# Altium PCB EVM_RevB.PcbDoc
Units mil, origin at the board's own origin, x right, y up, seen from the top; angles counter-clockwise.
Board outline 2000 x 3000 mil, 4 copper layers (Top Layer, Signal Layer 1, Signal Layer 2, Bottom Layer), stack 85.4 mil thick; 50 components, 21 nets, 126 pads, 89 vias.
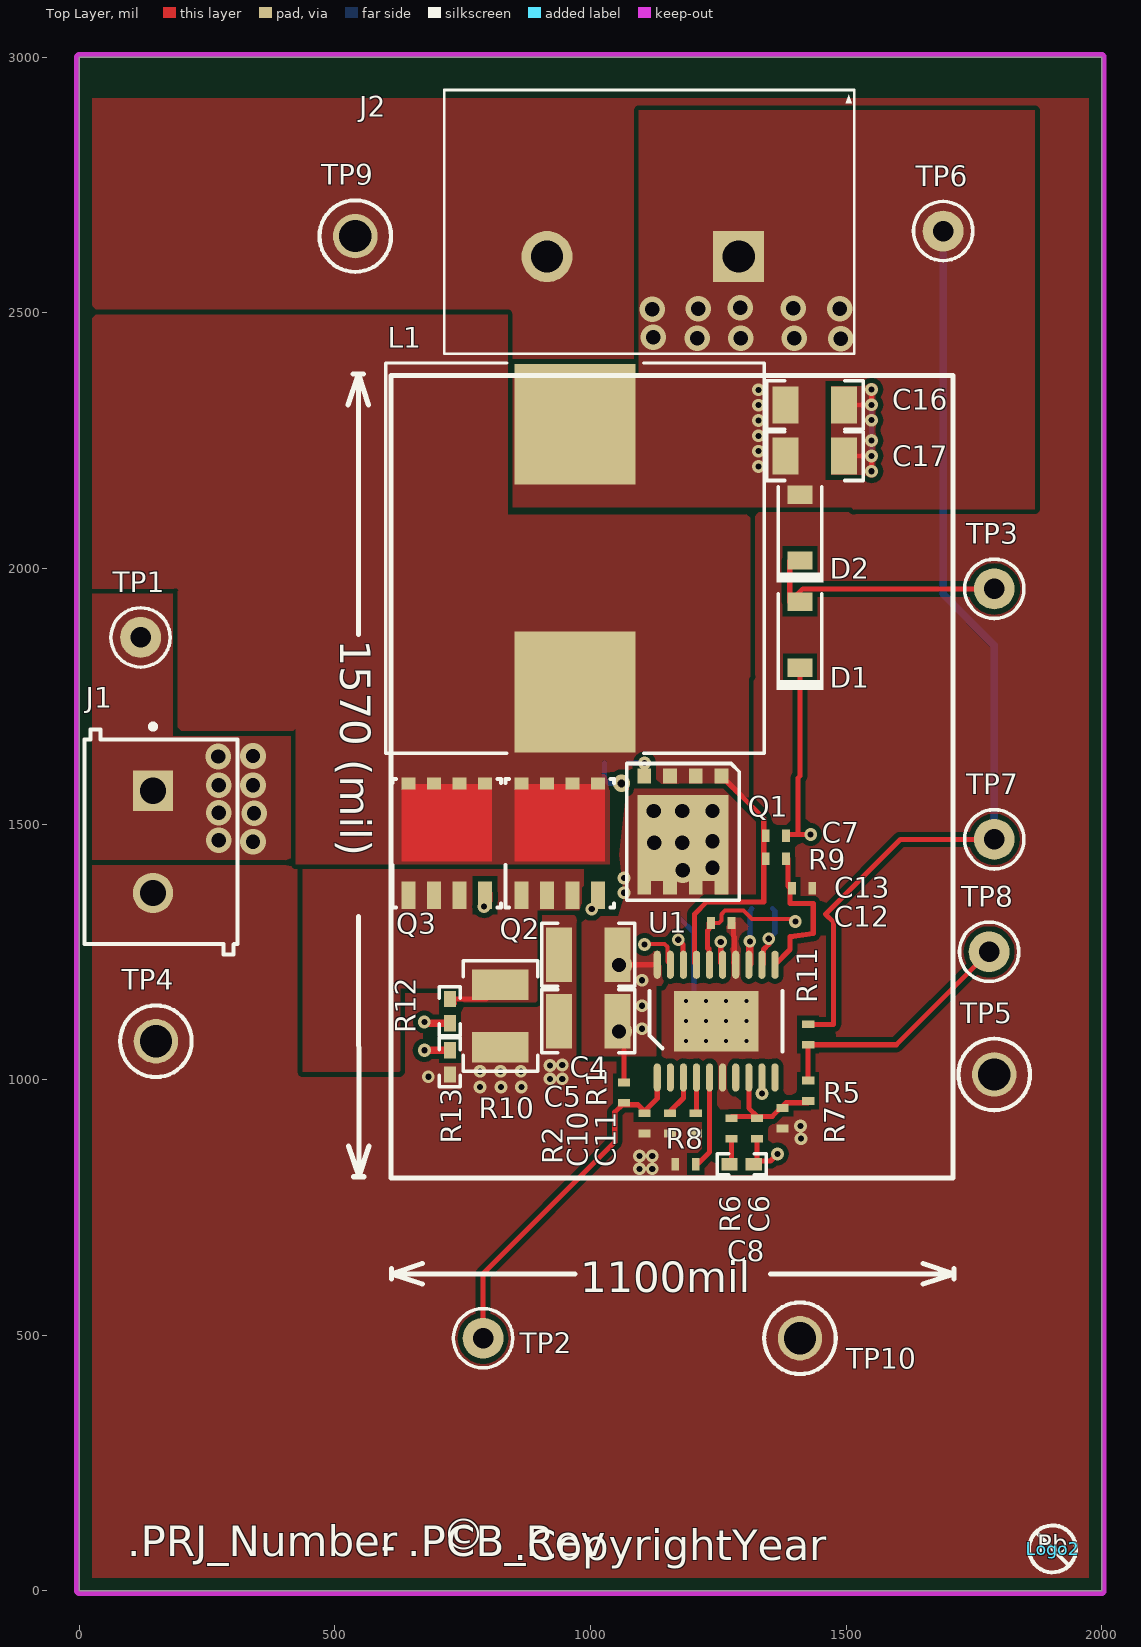
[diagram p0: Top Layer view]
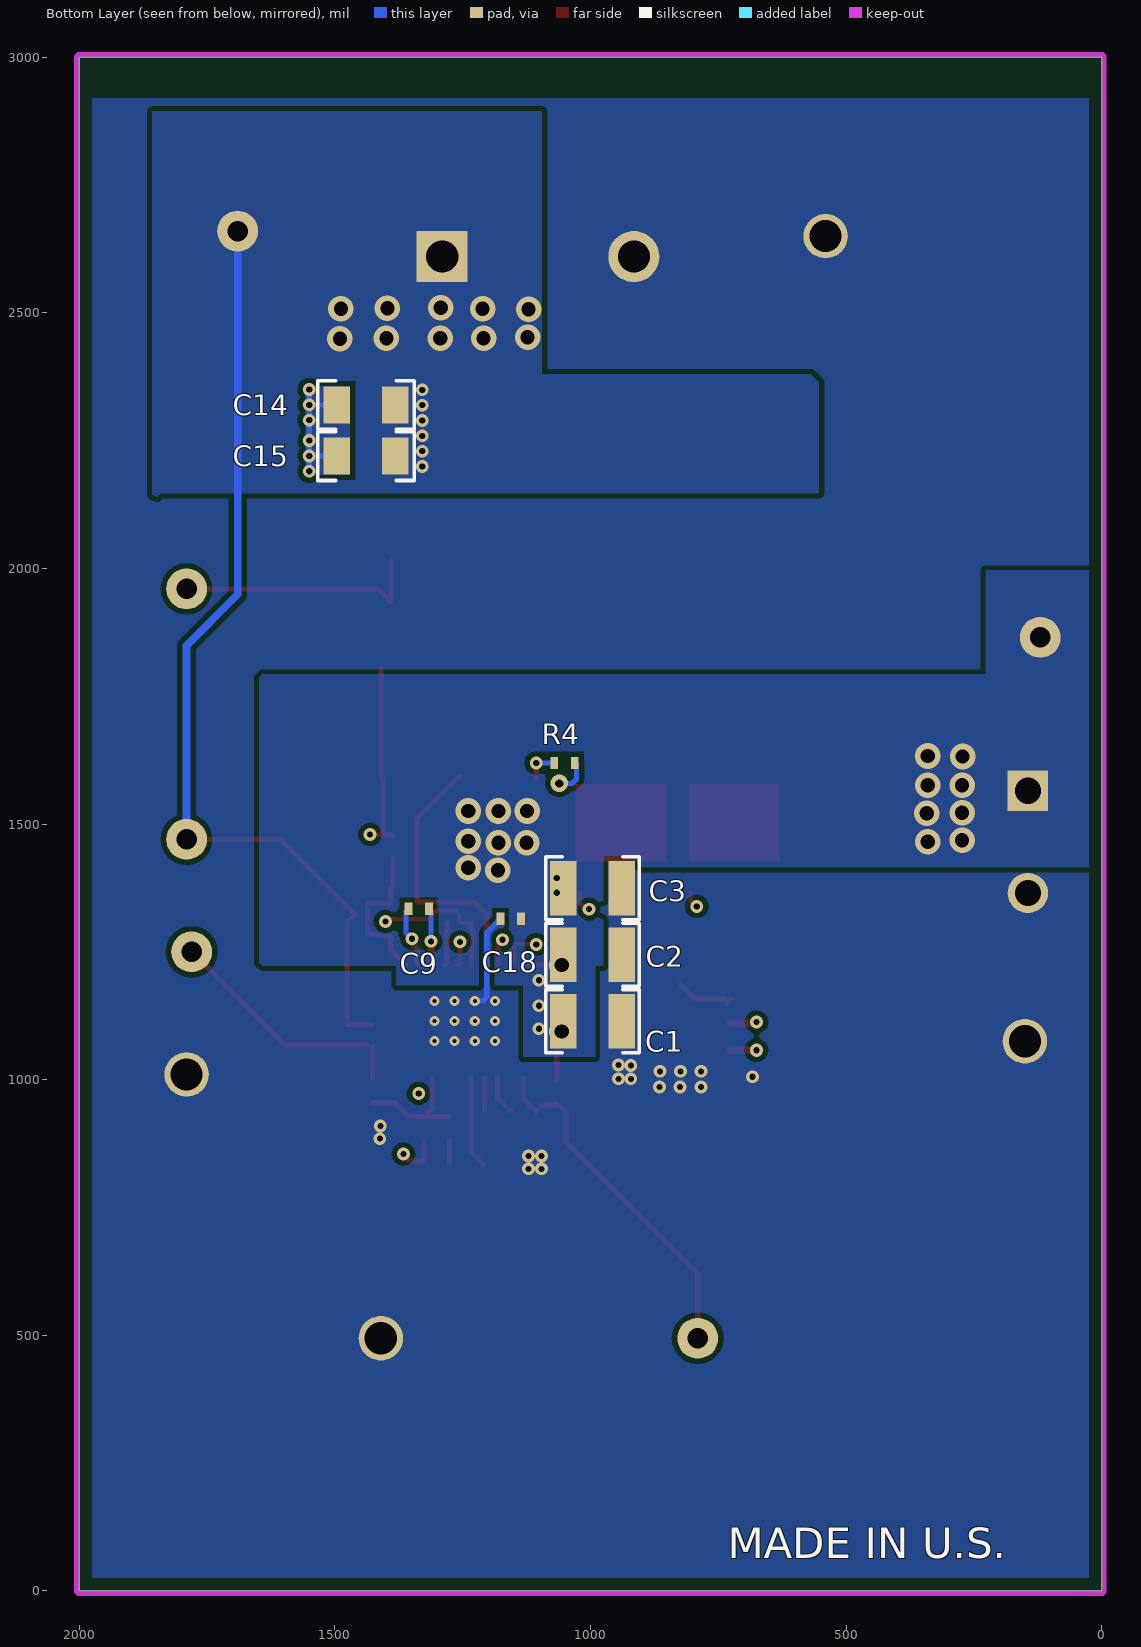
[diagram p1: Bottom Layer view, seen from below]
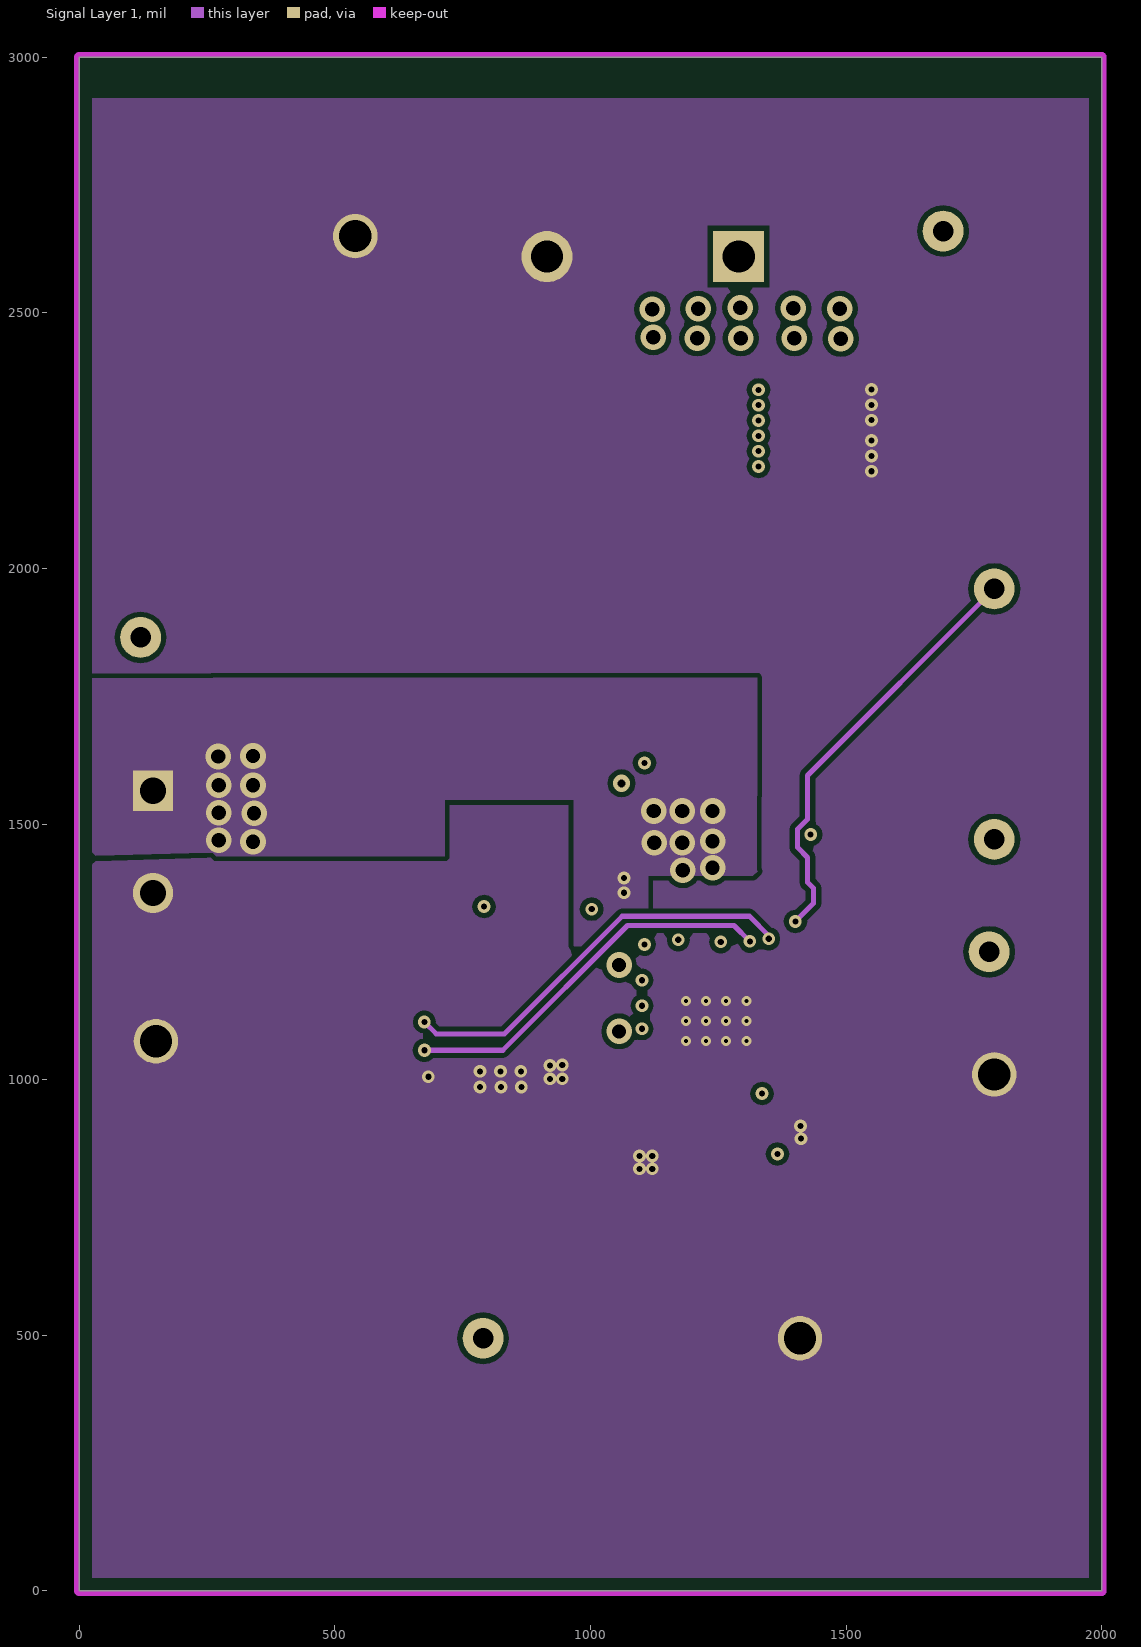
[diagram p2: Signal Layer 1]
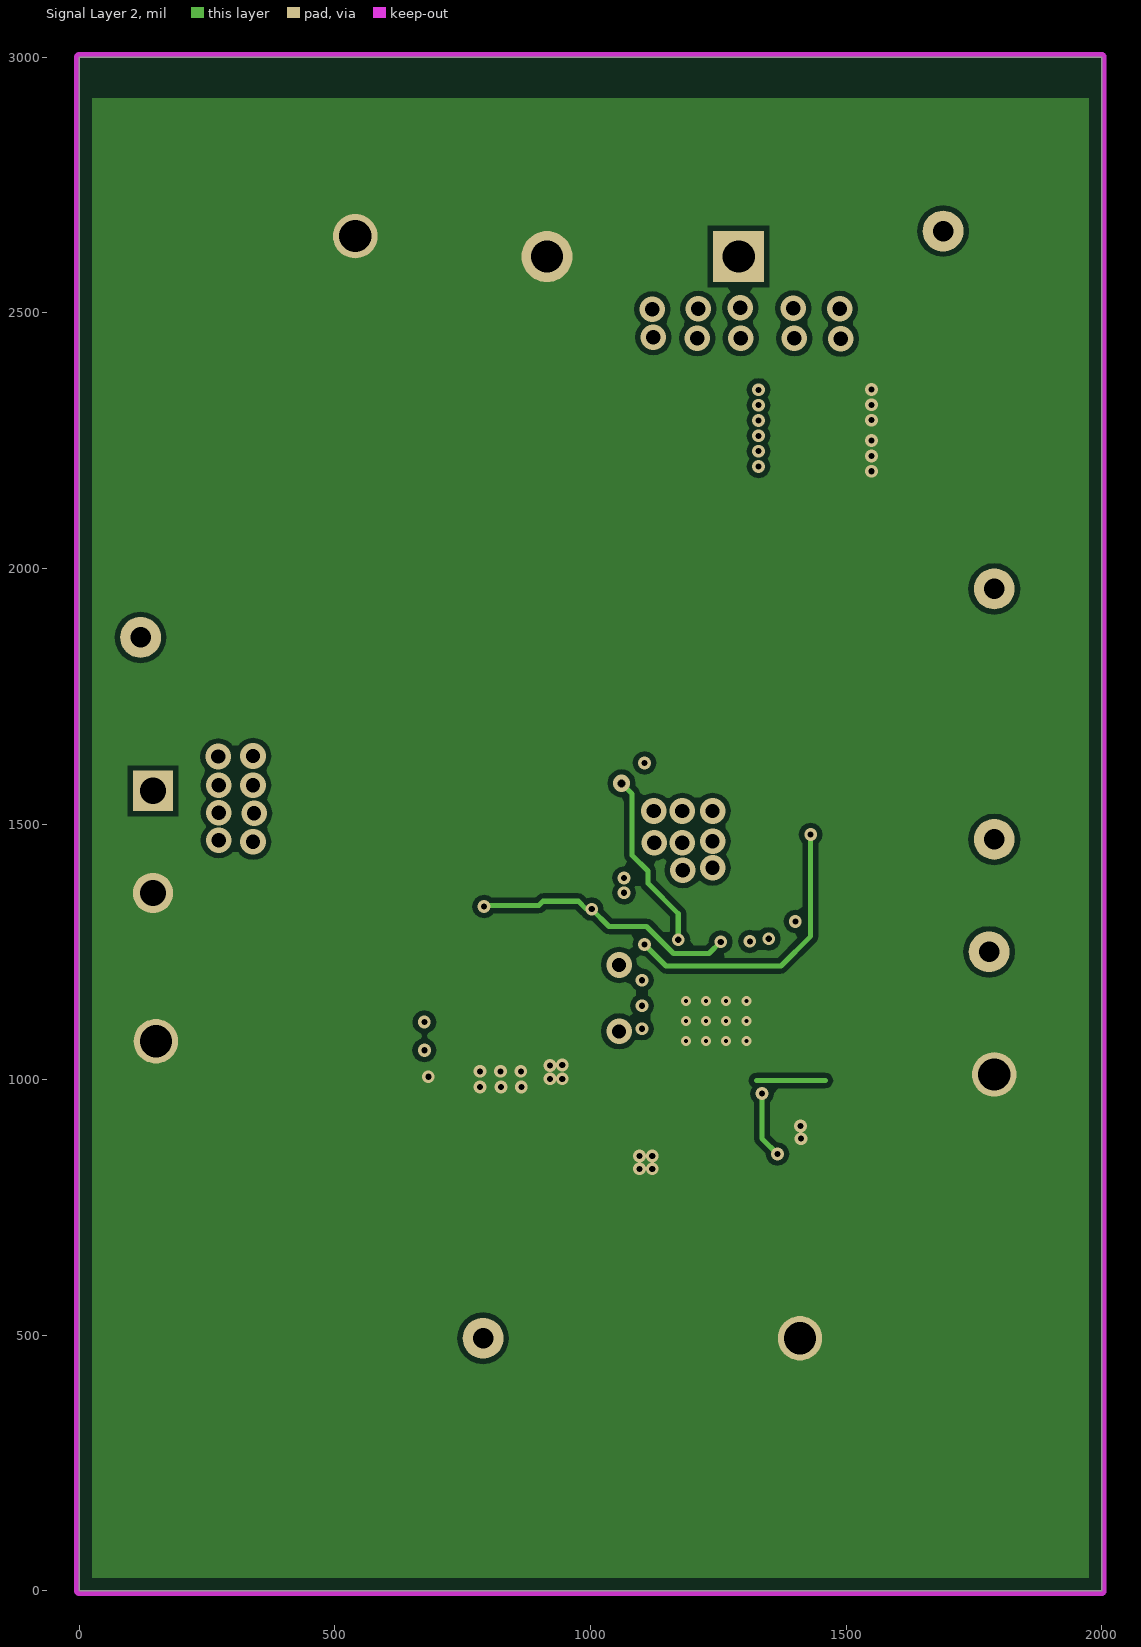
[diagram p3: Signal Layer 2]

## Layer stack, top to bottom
Top Solder: solder mask 0.4, Solder Resist, Dk 3.5
Top Layer: signal copper 2.8
Dielectric1: core 59.2, FR-4, Dk 4.8
Signal Layer 1: signal copper 2.8
Dielectric 3: prepreg 5, Dk 4.2
Signal Layer 2: signal copper 2.8
Dielectric 2: core 10, Dk 4.2
Bottom Layer: signal copper 2.8
Bottom Solder: solder mask 0.4, Solder Resist, Dk 3.5

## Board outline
0,0 2000,0 2000,3000 0,3000

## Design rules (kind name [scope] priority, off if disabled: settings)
AcuteAngle [All] p1: minimum=4.50000000000000E+0001 checktracksonly=FALSE
AssemblyTestPointUsage [All] p1: valid=2
Clearance Clearance_BoardEdge_MountingHoles [OnCopper and InComponentClass('Mounting Holes') vs IsKeepOut] p1: gap=40
Clearance Clearance_BoardEdge_Poly [OnCopper and InPoly vs IsKeepOut] p2: gap=25
Clearance Clearance_BoardEdge [OnCopper and Not InComponentClass('Logo') and not InComponentClass('FiducialMark') and not InRegion(1000,500,4000,800) and Not IsKeepout vs IsKeepOut] p3: gap=75
Clearance Clearance_Poly [InPolygon] p4: gap=10
Clearance [All] p5: gap=8
ComponentClearance ComponentClearance_ScrewToNut [(HasFootprint('NY PMS 440 0025 PH')) vs (HasFootprint('Keystone_1902C'))] p1: gap=5 collisioncheckmode=3 verticalgap=10 showdistances=FALSE
ComponentClearance ComponentClearance_MountingHoles [InComponentClass('Mounting Holes')] p2: gap=20 collisioncheckmode=3 verticalgap=100000 showdistances=FALSE
ComponentClearance ComponentClearance_SmallPassives [HasFootprint('0201*') or HasFootprint('0402*') or HasFootprint('0508') or HasFootprint('0603*') or HasFootprint('0612') or HasFootprint('0805*') or HasFootprint('0815*') or HasFootprint('0830*') or HasFootprint('1206*') or HasFootprint('1210*') or HasFootprint('1808*') or HasFootprint('1812*') or HasFootprint('1825*') or HasFootprint('2010*') or HasFootprint('2220*') or HasFootprint('2225*') or HasFootprint('2512*') or HasFootprint('2728*') or HasFootprint('3518*') vs HasFootprint('0201*') or HasFootprint('0402*') or HasFootprint('0508') or HasFootprint('0603*') or HasFootprint('0612') or HasFootprint('0805*') or HasFootprint('0815*') or HasFootprint('0830*') or HasFootprint('1206*') or HasFootprint('1210*') or HasFootprint('1808*') or HasFootprint('1812*') or HasFootprint('1825*') or HasFootprint('2010*') or HasFootprint('2220*') or HasFootprint('2225*') or HasFootprint('2512*') or HasFootprint('2728*') or HasFootprint('3518*')] p3: gap=10 collisioncheckmode=3 verticalgap=10 showdistances=FALSE
ComponentClearance ComponentClearance_THtoSMT [IsThruComponent vs IsSMTComponent] p4: gap=20 collisioncheckmode=3 verticalgap=100000 showdistances=FALSE
ComponentClearance ComponentClearance_THtoTH [IsThruComponent vs IsThruComponent] p5: gap=20 collisioncheckmode=3 verticalgap=100000 showdistances=FALSE
ComponentClearance [All] p6: gap=20 collisioncheckmode=3 verticalgap=10 showdistances=FALSE
DiffPairsRouting [All] p1: maxlimit=100 minlimit=10 mostfreqgap=10 toplayer_minwidth=15 toplayer_maxwidth=15 toplayer_prefwidth=15 midlayer1_minwidth=15 midlayer1_maxwidth=15 midlayer1_prefwidth=15 midlayer2_minwidth=15 midlayer2_maxwidth=15 midlayer2_prefwidth=15 bottomlayer_minwidth=15 bottomlayer_maxwidth=15 bottomlayer_prefwidth=15 maxuncoupledlength=1000
FabricationTestPointUsage TestPointUsage [All] p1: valid=2 allowmultiple=FALSE
FabricationTestpoint Testpoint [All] p1: side=3 testpointundercomponent=TRUE minsize=40 maxsize=100 preferedsize=60 minholesize=0 maxholesize=40 preferedholesize=32 testpointgrid=1 allowsidetop=TRUE allowsidebottom=TRUE usegrid=TRUE gridtolerance=0.01
FanoutControl Fanout_LCC [IsLCC] p1: bgadir=Out bgaviamode=Centered fanoutstyle=Auto fanoutdirection=Alternating viagrid=1 // Fanout_LCC (Default Rule)
FanoutControl Fanout_BGA [IsBGA] p2: bgadir=Out bgaviamode=Centered fanoutstyle=Auto fanoutdirection=Alternating viagrid=1 // Fanout_BGA (Default Rule)
FanoutControl Fanout_Default [All] p4: bgadir=Out bgaviamode=Centered fanoutstyle=Auto fanoutdirection=Alternating viagrid=1 // Fanout_Default (Default Rule)
FanoutControl Fanout_Small [(CompPinCount < 5)] p5: bgadir=Out bgaviamode=Centered fanoutstyle=Auto fanoutdirection=OutThenIn viagrid=1 // Fanout_Small (Default Rule)
HoleSize [All] p1: absolutevalues=TRUE maxlimit=251 minlimit=7 maxpercent=80.000 minpercent=20.000
MinimumAnnularRing [All] p1: minimumring=5
MinimumSolderMaskSliver MinimumSolderMaskSliver_Logo [InComponentClass('Logo') vs InComponentClass('Logo')] p1: minsoldermaskwidth=0
MinimumSolderMaskSliver SilkscreenOverComponentPads [All] p2: minsoldermaskwidth=0
MinimumSolderMaskSliver [All] p3: minsoldermaskwidth=0
PlaneConnect [All] p1: planeconnectstyle=Direct reliefexpansion=10 reliefentries=4 reliefconductorwidth=10 reliefairgap=10
PolygonConnect [All] p1: connectstyle=Direct reliefconductorwidth=10 reliefentries=4 polygonreliefangle="90 Angle" airgapwidth=10
RoutingVias [All] p1: holewidth=16 width=34 viastyle="Through Hole" minholewidth=7 minwidth=19 maxholewidth=40 maxwidth=65
SMDToCorner [All] p1: distance=0
SilkToSilkClearance [All] p1: silktosilkclearance=0
SilkToSolderMaskClearance [IsPad] p1: minsilkscreentomaskgap=0 clearancetoexposedcopper=TRUE
SolderMaskExpansion [All] p1: expansion=3
UnpouredPolygon [All] p1: allowunpoured=FALSE
Width [All] p1: maxlimit=100 minlimit=6 preferedwidth=10 checkconnectedcopper=TRUE
15 further rules are at their usual default settings.

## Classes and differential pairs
component class EVM_Hardware: Logo2
differential pair CS: +CS_P -CS_N

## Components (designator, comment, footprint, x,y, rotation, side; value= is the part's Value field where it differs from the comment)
C1 "GRM32ER71H106KA12L" 1210 995.91,1114.45 r180 bottom
C2 "GRM32ER71H106KA12L" 1210 995.91,1244.45 r180 bottom
C3 "GRM32ER71H106KA12L" 1210 995.91,1374.45 r180 bottom
C4 "GRM32ER71H106KA12L" 1210 995.91,1244.45 r180 top
C5 "GRM32ER71H106KA12L" 1210 995.91,1114.45 r180 top
C6 "CC0402JRNPO9BN101" 0402S 1325.91,904.45 r90 top
C7 "C1005X7R1H104K050BB" 0402S 1362.75,1476.93 r0 top
C8 "GRM155R61C103KA01D" 0402 1295.91,834.45 r180 top
C9 "GRM155R72A102KA01D" 0402S 1335.91,1334.45 r180 bottom
C10 "GRM155C80G474KE01D" 0402S 1155.91,914.45 r270 top
C11 "C1005X5R1C105K050BC" 0402S 1205.91,914.45 r270 top
C12 "GRM155R61E475ME15" 0402S 1255.91,1306.45 r180 top
C13 "GRM155R72A102KA01D" 0402S 1414.25,1374.45 r0 top
C14 "C3216X5R1E476M160AC" 1206 1439,2319.69 r0 bottom
C15 "C3216X5R1E476M160AC" 1206 1439,2219.69 r0 bottom
C16 "C3216X5R1E476M160AC" 1206 1439,2319.69 r0 top
C17 "C3216X5R1E476M160AC" 1206 1439,2219.69 r0 top
C18 "C1005X7R1H104K050BB" 0402S 1155.91,1314.45 r0 bottom
D1 "1N5819HW-7-F" SOD-123 1410,1870 r90 top
D2 "1N5819HW-7-F" SOD-123 1410,2080 r90 top
J1 "OSTTC022162" On-Shore_OSTTC022162 160,1465 r270 top
J2 "OSTT7022150" TERM_BLK_OSTT7022150 1290,2610 r180 top
L1 "74435571100" WE-HCB_1890 970,2020 r90 top
Logo2 "Pb-Free Symbol" Pb-Free_Overlay_Small 1904,82 r0 top
Q1 "CSD18563Q5A" TRANS_NexFET_Q5A 1180.91,1484.45 r270 top
Q2 "CSD18532Q5B" TRANS_NexFET_Q5B 940,1470 r90 top
Q3 "CSD18532Q5B" TRANS_NexFET_Q5B 719,1470 r90 top
R1 "CRCW0402100KFKED" 0402S 1065.91,974.45 r90 top
R2 "CRCW04029K76FKED" 0402S 1105.91,914.45 r270 top
R4 "CRCW04020000Z0ED" 0402S 1050.91,1619.45 r0 bottom
R5 "CRCW040210K5FKED" 0402S 1425.91,978.25 r270 top
R6 "CRCW04023K48FKED" 0402S 1275.91,904.45 r270 top
R7 "CRCW0402750RFKED" 0402S 1375.91,924.45 r90 top
R8 "CRCW040224K9FKED" 0402S 1185.91,834.45 r0 top
R9 "CRCW0402133KFKED" 0402S 1362.75,1431.93 r180 top
R10 "PMR25HZPFU5L00" 1210M 823.91,1124.45 r90 top
R11 "CRCW040249R9FKED" 0402S 1425.91,1088.25 r90 top
R12 "CRCW0402100RFKED" 0402 725.09,1133.83 r90 top
R13 "CRCW0402100RFKED" 0402 725.09,1033.83 r270 top
TP1 "5000" Keystone5000 120,1865 r180 top
TP2 "5000" Keystone5000 790,494 r0 top
TP3 "5000" Keystone5000 1790,1960 r0 top
TP4 "5011" Keystone5011 150,1075 r180 top
TP5 "5011" Keystone5011 1790,1010 r0 top
TP6 "5000" Keystone5000 1690,2660 r180 top
TP7 "5000" Keystone5000 1790,1470 r0 top
TP8 "5000" Keystone5000 1780,1250 r0 top
TP9 "5011" Keystone5011 540,2650 r180 top
TP10 "5011" Keystone5011 1410,494 r0 top
U1 "LM5117QPMH/NOPB" PWP0020A_L 1245.91,1114.45 r90 top

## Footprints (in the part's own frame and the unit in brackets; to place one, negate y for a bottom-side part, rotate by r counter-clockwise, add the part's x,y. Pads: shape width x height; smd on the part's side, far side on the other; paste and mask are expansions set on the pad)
0402 [mm] "0402 from SM-752 data"
  rect 0.8x0.6 smd: 1(-0.6,0) 2(0.6,0)
  silkscreen extent -1.22,-0.52 1.22,0.52, body extent -0.55,-0.3 0.55,0.3, height 0.6
0402S [mil] "Based on C0402S footprint from PADS legacy"
  rect 15x24 smd: 1(-20,0) 2(20,0)
  body extent -22,-12 22,12, height 24
1206 [mm] "1206 from SM-752 data"
  rect 1.3x1.85 smd: 1(-1.45,0) 2(1.45,0)
  silkscreen extent -2.4,-1.21 2.4,1.21, body extent -1.7,-0.9 1.7,0.9, height 1.35
1210 [mm] "1210 from SM-752 data"
  rect 1.3x2.7 smd: 1(-1.45,0) 2(1.45,0)
  silkscreen extent -2.32,-1.57 2.32,1.57, body extent -1.7,-1.35 1.7,1.35, height 1.35
1210M [mm] "1210 from SM-752 data"
  rect 1.5x2.8 smd: 1(-1.55,0) 2(1.55,0)
  silkscreen extent -2.75,-1.85 2.75,1.85, body extent -1.7,-1.35 1.7,1.35, height 1.35
Keystone5000 [mil] "For Keystone 500x miniature loop terminals"
  round 80 hole 40: 1(0,0)
  silkscreen extent -58,-58 58,58, body extent -49,-49 49,49, height 182
Keystone5011 [mil] "Keystone Multipurpose loops"
  round 87 hole 63: 1(0,0)
  silkscreen extent -70,-70 70,70, body extent -63,-63 63,62, height 319
On-Shore_OSTTC022162 [mm] "THD, 2-Leads, Body 10.16x7.6mm, Pitch 5.08mm"
  rect 2x2 hole 1.3: 1(-2.54,-0.4)
  round 2 hole 1.3: 2(2.54,-0.4)
  silkscreen extent -5.85,-3.8 5.6,3.8, body extent -5.58,-3.8 5.6,3.8, height 10.31
Pb-Free_Overlay_Small [mil]
  silkscreen extent -46,-46 46,46
PWP0020A_L [mm] "TSOP, 20-Leads, Body 6.5x4.4mm, Pitch 0.65mm, Exposed Pad, IPC High Density"
  oval 1.4x0.35 smd: 1(-2.8,2.925) 2(-2.8,2.275) 3(-2.8,1.625) 4(-2.8,0.975) 5(-2.8,0.325) 6(-2.8,-0.325) 7(-2.8,-0.975) 8(-2.8,-1.625) 9(-2.8,-2.275) 10(-2.8,-2.925) 11(2.8,-2.925) 12(2.8,-2.275) 13(2.8,-1.625) 14(2.8,-0.975) 15(2.8,-0.325) 16(2.8,0.325) 17(2.8,0.975) 18(2.8,1.625) 19(2.8,2.275) 20(2.8,2.925)
  rect 3x4.2 smd: 21(0,0)
  silkscreen extent -1.5,-3.3 1.5,3.3, body extent -3.21,-3.25 3.21,3.25, height 0.98
SOD-123 [mm] "On Semi recommended land pattern"
  rect 0.915x1.22 smd: 1(-1.637,0) 2(1.637,0)
  silkscreen extent -2.74,-1.17 2.03,1.17, body extent -1.93,-0.9 1.93,0.9, height 1.35
TERM_BLK_OSTT7022150 [mm]
  rect 2.54x2.54 hole 1.6: 1(0,0)
  round 2.54 hole 1.6: 2(9.525,0)
  silkscreen extent -5.74,-8.28 14.63,4.83, body extent -5.3,-8 14.33,4.5, height 21.6
TRANS_NexFET_Q5A [mm] "TI recommended land pattern (nominal) M0139-01"
  rect 0.75x0.675 smd paste-0.1 mask+0.051: 1(-2.776,1.917) 2(-2.776,0.639) 3(-2.776,-0.639) 4(-2.776,-1.917)
  rect 0.655x0.675 smd paste-0.1 mask+0.051: 5(2.776,-1.917) 6(2.776,-0.639) 7(2.776,0.639) 8(2.776,1.917)
  rect 4.295x4.51 smd paste-2.2 mask+0.051: 9(0.301,0)
  silkscreen extent -3.4,-2.8 3.4,2.8, body extent -3.05,-2.5 3.05,2.5, height 1.11
TRANS_NexFET_Q5B [mm] "TI recommended land pattern (nominal) November 2012"
  rect 1.372x0.71 smd paste-0.4: 1(-2.776,1.905) 2(-2.776,0.635) 3(-2.776,-0.635) 4(-2.776,-1.905)
  rect 0.59x0.71 smd paste-0.3: 5(2.776,-1.905) 6(2.776,-0.635) 7(2.776,0.635) 8(2.776,1.905)
  Top Layer region: -1.106,-2.26 2.744,-2.26 2.744,2.26 -1.106,2.26
  silkscreen extent -3.38,-2.7 3,2.7, body extent -3.23,-2.55 2.87,2.55, height 1.06
WE-HCB_1890 [mm] "WURTH ELEKTRONIK"
  rect 6x6 smd: 1(-6.65,0) 2(6.65,0)
  silkscreen extent -9.7,-9.4 9.7,9.4, body extent -9.65,-9.35 9.65,9.35, height 9.2

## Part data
C1 C2 C3 C4 C5: "CAP, CERM, 10 µF, 50 V, +/- 10%, X7R, 1210"
C6: "CAP, CERM, 100 pF, 50 V, +/- 5%, C0G/NP0, 0402"
C7 C18: "CAP, CERM, 0.1 µF, 50 V, +/- 10%, X7R, 0402"
C8: "CAP, CERM, 0.01 µF, 16 V, +/- 10%, X5R, 0402"
C9 C13: "CAP, CERM, 1000 pF, 100 V, +/- 10%, X7R, 0402"
C10: "CAP, CERM, 0.47 µF, 4 V, +/- 10%, X6S, 0402"
C11: "CAP, CERM, 1 µF, 16 V, +/- 10%, X5R, 0402"
C12: "CAP, CERM, 4.7 µF, 25 V, +/- 20%, X5R, 0402"
C14 C15 C16 C17: "CAP, CERM, 47 µF, 25 V, +/- 20%, X5R, 1206"
D1 D2: "Diode, Schottky, 40 V, 1 A, SOD-123"
J1: "Terminal Block, 2-pole, 200mil, TH"
J2: "Terminal Block, 30A, 9.52mm (.375) Pitch, 2-Pos, TH"
L1: "Inductor, Shielded Drum Core, Ferrite, 10 µH, 16.5 A, 0.0069 ohm, SMD"
Logo2: library part Pb-Free
Q1: "MOSFET, N-CH, 60 V, 15 A, SON 5x6mm"
Q2 Q3: "MOSFET, N-CH, 60 V, 172 A, SON 5x6mm"
R1: "RES, 100 k, 1%, 0.063 W, 0402"
R2: "RES, 9.76 k, 1%, 0.063 W, 0402"
R4: "RES, 0, 5%, 0.063 W, 0402"
R5: "RES, 10.5 k, 1%, 0.063 W, 0402"
R6: "RES, 3.48 k, 1%, 0.063 W, 0402"
R7: "RES, 750, 1%, 0.063 W, 0402"
R8: "RES, 24.9 k, 1%, 0.063 W, 0402"
R9: "RES, 133 k, 1%, 0.063 W, 0402"
R10: "RES, 0.005, 1%, 1 W, 1210"
R11: "RES, 49.9, 1%, 0.063 W, 0402"
R12 R13: "RES, 100, 1%, 0.063 W, 0402"
TP1 TP2 TP3 TP6 TP7 TP8: "Test Point, Miniature, Red, TH"
TP4 TP5 TP9 TP10: "Test Point, Multipurpose, Black, TH"
U1: "Wide Input Range Synchronous Buck Controller with Analog Current Monitor, PWP0020A"

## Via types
v1: diameter 25, hole 12, Top Layer to Bottom Layer, 47 vias
v2: diameter 50, hole 28, Top Layer to Bottom Layer, 28 vias
v3: diameter 19.68, hole 7.87, Top Layer to Bottom Layer, 12 vias
v4: diameter 34, hole 16, Top Layer to Bottom Layer, 1 vias
v5: diameter 26, hole 12, Top Layer to Bottom Layer, 1 vias

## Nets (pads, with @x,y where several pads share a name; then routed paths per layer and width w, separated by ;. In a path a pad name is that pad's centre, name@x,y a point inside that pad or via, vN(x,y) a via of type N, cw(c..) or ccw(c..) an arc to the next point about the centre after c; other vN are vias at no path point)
12VOUT: C14.1 C15.1 C16.1 C17.1 D2.2 J2.1 L1.2 R11.2 TP6.1 TP7.1 | length 1850.4
  Top Layer w10: R11.2@1429.71,1108.07 1475.91,1108.07 1475.91,1307.71 1460,1323.62 1606.38,1470 TP7.1
  Bottom Layer w15: 1690,2620 1690,1949.25 1790,1849.25 TP7.1
  other v1: 1329,2199.37 1329,2229.37 1329,2259.37 1329,2289.37 1329,2319.37 1329,2349.37
  other v2: 1490,2449 1209,2450 1294,2450 1399,2450 1123,2452 1121,2507 1211,2508 1488,2508 1397,2509 1293,2510
CS_N: C9.2 R13.1 U1.13 | length 909.8
  Top Layer w15: v5(675.27,1057.46) R13.1 ; U1.13@1311.91,1226.71 v1(1311.91,1270.45)
  Signal Layer 1 w10: v5(675.27,1057.46) 828.6,1057.46 1072.59,1301.45 1280.91,1301.45 v1(1311.91,1270.45)
  Bottom Layer w10: v1(1311.91,1270.45) 1311.91,1330.45 C9.2
CS_P: C9.1 R12.1 U1.12 | length 956.2
  Top Layer w10: U1.12@1338.8,1226.58 1338.8,1254.57 v1@1348.91,1264.68
  Top Layer w15: v1@677.52,1110.21 R12.1
  Signal Layer 1 w10: v1(675.09,1112.63) 698.28,1089.45 832.12,1089.45 1062.12,1319.45 1311.07,1319.45 1348.91,1281.6 v1(1348.91,1275.45)
  Bottom Layer w10: v1(1348.91,1275.45) 1360.59,1287.13 1360.59,1329.76 C9.1
GND: C1.2 C2.2 C3.2 C4.2 C5.2 C10.2 C11.2 C12.1 C13.2 C14.2 C15.2 C16.2 C17.2 C18.2 J1.2 J2.2 R2.2 R7.1 R8.1 R10.1 R13.2 TP4.1 TP5.1 TP9.1 TP10.1 U1.6 U1.14 U1.21 | length 710.8
  Top Layer w10: C12.1@1279.53,1306.45 1280.03,1305.94 1280.03,1280.21 1281.28,1278.96 1281.28,1228.94 1280.03,1228.94 U1.14 ; C17.2 v1@1549.69,2219.69 ; C16.2 v1@1549.69,2319.69 ; v1(1550,2190) v1(1550,2220) ; v1(1550,2320) v1(1550,2350)
  Bottom Layer w10: C18.2 1202.7,1287.66 1202.7,1161.24 1210.12,1153.82 v3(1226.22,1153.82) ; C15.2 v1@1549.69,2219.69 ; C14.2 v1@1549.69,2319.69 ; v1(1550,2190) v1(1550,2220) v1(1550,2250) v1(1550,2290) v1(1550,2320) v1(1550,2350)
  other v1: 1095.91,825.45 1120.91,825.45 1095.91,850.45 1120.91,850.45 1411.91,884.45 1410.91,909.45 783.91,985.45 824.91,985.45 864.91,985.45 920.91,1001.45 944.91,1001.45 682.91,1005.45 783.91,1016.18 823.91,1016.18 863.91,1016.18 920.91,1027.45 944.91,1028.45
  other v3: 1186.85,1075.08 1226.22,1075.08 1265.59,1075.08 1304.96,1075.08 1186.85,1114.45 1226.22,1114.45 1265.59,1114.45 1304.96,1114.45 1186.85,1153.82 1265.59,1153.82 1304.96,1153.82
NetC6_1: C6.1 C8.1 U1.9 | length 216.3
  Top Layer w10: C6.1@1325.91,880.83 1325.91,840.83 1352.29,840.83 v1(1365.91,854.45)
  Signal Layer 2 w10: v1(1335.91,972.72) 1335.91,884.45 v1(1365.91,854.45)
NetC6_2: C6.2 R5.2 R6.1 R7.2 U1.8 | length 243.8
  Top Layer w10: R6.1@1275.91,928.07 C6.2@1325.91,928.07 ; U1.8 1309.88,944.09 C6.2@1325.91,928.07 ; R5.2@1425.91,954.62 1382.46,954.62 1375.91,948.07 1355.91,928.07 C6.2@1325.91,928.07
NetC7_1: C7.1 L1.1 Q1.1 Q1.2 Q1.3 Q2.5 Q2.6 Q2.7 Q2.8 Q3.5 Q3.6 Q3.7 Q3.8 R9.2 U1.17 | length 526.3
  Top Layer w10: U1.17 1203.66,1228.54 1203.66,1323.59 1227.74,1347.67 1339.13,1347.67 1339.13,1431.93 1339.13,1511.02 Q1.1
NetC7_2: C7.2 D1.1 U1.19 | length 1016.7
  Top Layer w8: v1@1106.58,1265.12 1145.24,1265.12 1150.53,1259.82 1150.53,1230.49 U1.19
  Top Layer w10: C7.2@1386.38,1476.93 1388.89,1479.45 1405.91,1479.45 ; 1405.91,1589.98 1405.91,1479.45 ; 1410,1594.07 D1.1 ; v1(1430.91,1479.45) 1405.91,1479.45
  Signal Layer 2 w10: v1(1105.91,1264.45) 1147.98,1222.37 1372.69,1222.37 1430.91,1280.59 v1(1430.91,1479.45)
NetC8_2: C8.2 R6.2 | length 42.8
  Top Layer w10: C8.2@1275.91,838.07 R6.2@1275.91,880.83
NetC10_1: C10.1 U1.3 | length 76.9
  Top Layer w10: C10.1@1155.91,938.07 1181.93,964.09 U1.3
NetC11_1: C11.1 U1.4 | length 64.5
  Top Layer w10: C11.1@1207.52,939.68 U1.4
NetC13_1: C13.1 R9.1 U1.11 | length 306
  Top Layer w10: U1.11 1390.63,1254.25 1390.63,1279.45 1435.86,1285.54 1435.86,1344.4 1390.63,1344.4 1390.63,1374.45 1386.38,1378.7 R9.1@1386.38,1431.93
NetQ1_4: Q1.4 R4.2 | length 62.6
  Top Layer w10: Q1.4@1105.91,1588.26 v1(1105.91,1619.45)
  Bottom Layer w10: R4.2@1074.53,1619.45 v1(1105.91,1619.45)
NetQ2_1: Q2.1 Q2.2 Q2.3 Q3.1 Q3.2 Q3.3 R10.2 R12.2 | length 111.1
  Top Layer w10: R12.2 R12.2@733.89,1148.66 ; 736.9,1157.46 795.89,1157.46 R10.2
NetQ2_4: Q2.4 Q3.4 U1.15 | length 635
  Top Layer w10: v1(791.91,1338.45) 803.4,1349.94 Q3.4@803.4,1365.14 ; v1(1002.53,1333.37) 1007.96,1333.37 1021.4,1346.81 Q2.4@1021.4,1365.14 ; v1(1254.91,1269.45) 1254.91,1228.48 U1.15
  Signal Layer 2 w10: v1@795.91,1340.45 898.85,1340.45 907.35,1348.95 976.47,1348.95 992.04,1333.37 v1(1002.53,1333.37) 1036.46,1299.45 1109.85,1299.45 1162.79,1246.51 1231.97,1246.51 v1(1254.91,1269.45)
NetR1_1: R1.1 R2.1 TP2.1 U1.1 | length 685.7
  Top Layer w10: TP2.1 790,620 1047.56,878 1047.56,936.1 R1.1@1058.41,946.95 ; R1.1@1065.91,950.83 1093.15,950.83 1105.91,938.07 1130.75,962.91 U1.1
NetR4_1: R4.1 U1.18 | length 499.8
  Top Layer w10: v4(1060.91,1579.45) v4@1070.87,1569.49 ; v1@1175.91,1269.45 1180.91,1264.45 1180.91,1225.71 U1.18
  Signal Layer 2 w10: v4@1060.91,1567.26 v4(1060.91,1579.45) 1081.41,1558.95 1081.41,1460.05 1081.45,1460.01 1081.45,1438.81 1112.42,1407.83 1112.42,1383.96 1171.91,1324.47 v1(1171.91,1273.45)
  Bottom Layer w10: R4.1@1027.29,1619.45 1027.29,1588.03 1035.87,1579.45 v4(1060.91,1579.45) ; v1(1171.91,1273.45) v1@1175.91,1269.45
NetR5_1: R5.1 R11.1 TP8.1 | length 480.1
  Top Layer w10: R5.1@1425.91,1001.87 R11.1@1425.91,1064.63 ; 1437.91,1068.25 1598.25,1068.25 TP8.1
NetR8_2: R8.2 U1.5 | length 179.5
  Top Layer w10: R8.2@1209.53,834.45 1233.11,858.03 U1.5
VCC: C12.2 D1.2 D2.1 TP3.1 U1.16 | length 1602.4
  Top Layer w8: C12.2@1232.29,1306.45 C12.2 1251.91,1306.45 1256.41,1310.95 1256.41,1323.42 1263.44,1330.45 1299.88,1330.45 1315.88,1314.45 v1@1395.89,1314.45
  Top Layer w10: C12.2@1232.29,1306.45 1232.29,1294.45 1229.41,1291.57 1229.41,1256.31 1229.53,1256.19 1232.29,1256.19 1232.29,1225.51 U1.16 ; D2.1@1390,2015.53 1390,1934.47 1415.53,1960 TP3.1
  Signal Layer 1 w10: v1(1400.91,1309.45) 1436.12,1344.66 1436.12,1374.66 1424.68,1386.1 1424.68,1434.67 1405.41,1453.95 1405.41,1490.01 1424.68,1509.28 1424.68,1594.68 TP3.1
VIN: C1.1 C2.1 C3.1 C4.1 C5.1 C18.1 J1.1 Q1.5 Q1.6 Q1.7 Q1.8 Q1.9 R1.2 TP1.1 U1.20 | length 186.2
  Top Layer w10: C4.1 1072.76,1224.68 U1.20 ; v2(1056.03,1094.22) 1065.91,1084.34 R1.2@1065.91,998.07
  other v1: 1100.91,1099.45 1100.91,1144.45 1100.91,1194.45 1065.91,1365.45 1065.91,1394.45
  other v2: 1056.03,1224.22 1180.91,1409.45 1238.91,1414.45 1124.91,1463.45 1179.91,1463.45 340,1465 1238.91,1466.45 273,1468 342,1521 273,1522 1123.91,1525.45 1179.91,1525.45 1238.91,1525.45 273,1576 340,1576 272,1632 340,1633
pads on no net: U1.2 U1.7 U1.10
copper on no net: | length 104184.8
  Signal Layer 2 w10: 1325.35,998.22 1459.42,998.22
  Bottom Layer w1: 13159.2,6090.32 13258.89,6190 13378.89,6310 13498.89,6430 13618.89,6550 13738.89,6670 13858.89,6790 13978.89,6910 14098.89,7030 14218.89,7150 14278.89,7210 ; 13159.2,6150.32 13198.89,6190 13318.89,6310 13438.89,6430 13558.89,6550 13678.89,6670 13798.89,6790 13918.89,6910 14038.89,7030 14158.89,7150 14278.89,7270 ; 13159.2,6210.32 13258.89,6310 13378.89,6430 13498.89,6550 13618.89,6670 13738.89,6790 13858.89,6910 13978.89,7030 14098.89,7150 14218.89,7270 14278.89,7330 ; 13159.2,6270.32 13198.89,6310 13318.89,6430 13438.89,6550 13558.89,6670 13678.89,6790 13798.89,6910 13918.89,7030 14038.89,7150 14158.89,7270 14278.89,7390 ; 13159.2,6330.32 13258.89,6430 13378.89,6550 13498.89,6670 13618.89,6790 13738.89,6910 13858.89,7030 13978.89,7150 14098.89,7270 14218.89,7390 ; 13159.2,6390.32 13198.89,6430 13318.89,6550 13438.89,6670 13558.89,6790 13678.89,6910 13798.89,7030 13918.89,7150 14038.89,7270 14158.89,7390 ; 13159.2,6450.32 13258.89,6550 13378.89,6670 13498.89,6790 13618.89,6910 13738.89,7030 13858.89,7150 13978.89,7270 14098.89,7390 ; 13159.2,6510.32 13198.89,6550 13318.89,6670 13438.89,6790 13558.89,6910 13678.89,7030 13798.89,7150 13918.89,7270 14038.89,7390 ; 13159.2,6570.32 13258.89,6670 13378.89,6790 13498.89,6910 13618.89,7030 13738.89,7150 13858.89,7270 13978.89,7390 ; 13159.2,6630.32 13198.89,6670 13318.89,6790 13438.89,6910 13558.89,7030 13678.89,7150 13798.89,7270 13918.89,7390 ; 13159.2,6690.32 13258.89,6790 13378.89,6910 13498.89,7030 13618.89,7150 13738.89,7270 13858.89,7390 ; 13159.2,6750.32 13198.89,6790 13318.89,6910 13438.89,7030 13558.89,7150 13678.89,7270 13798.89,7390 ; 13159.2,6810.32 13258.89,6910 13378.89,7030 13498.89,7150 13618.89,7270 13738.89,7390 ; 13159.2,6870.32 13198.89,6910 13318.89,7030 13438.89,7150 13558.89,7270 13678.89,7390 ; 13159.2,6930.32 13258.89,7030 13378.89,7150 13498.89,7270 13618.89,7390 ; 13159.2,6990.32 13198.89,7030 13318.89,7150 13438.89,7270 13558.89,7390 ; 13159.2,7050.32 13258.89,7150 13378.89,7270 13498.89,7390 ; 13159.2,7110.32 13198.89,7150 13318.89,7270 13438.89,7390 ; 13159.2,7170.32 13258.89,7270 13378.89,7390 ; 13159.2,7230.32 13198.89,7270 13318.89,7390 ; 13159.2,7290.32 13258.89,7390 ; 13159.2,7350.32 13198.89,7390 ; 13198.89,6070 13318.89,6190 13438.89,6310 13558.89,6430 13678.89,6550 13798.89,6670 13918.89,6790 14038.89,6910 14158.89,7030 14278.89,7150 ; 13258.89,6070 13378.89,6190 13498.89,6310 13618.89,6430 13738.89,6550 13858.89,6670 13978.89,6790 14098.89,6910 14218.89,7030 14278.89,7090 ; 13318.89,6070 13438.89,6190 13558.89,6310 13678.89,6430 13798.89,6550 13918.89,6670 14038.89,6790 14158.89,6910 14278.89,7030 ; 13378.89,6070 13498.89,6190 13618.89,6310 13738.89,6430 13858.89,6550 13978.89,6670 14098.89,6790 14218.89,6910 14278.89,6970 ; 13438.89,6070 13558.89,6190 13678.89,6310 13798.89,6430 13918.89,6550 14038.89,6670 14158.89,6790 14278.89,6910 ; 13498.89,6070 13618.89,6190 13738.89,6310 13858.89,6430 13978.89,6550 14098.89,6670 14218.89,6790 14278.89,6850 ; 13558.89,6070 13678.89,6190 13798.89,6310 13918.89,6430 14038.89,6550 14158.89,6670 14278.89,6790 ; 13618.89,6070 13738.89,6190 13858.89,6310 13978.89,6430 14098.89,6550 14218.89,6670 14278.89,6730 ; 13678.89,6070 13798.89,6190 13918.89,6310 14038.89,6430 14158.89,6550 14278.89,6670 ; 13738.89,6070 13858.89,6190 13978.89,6310 14098.89,6430 14218.89,6550 14278.89,6610 ; 13798.89,6070 13918.89,6190 14038.89,6310 14158.89,6430 14278.89,6550 ; 13858.89,6070 13978.89,6190 14098.89,6310 14218.89,6430 14278.89,6490 ; 13918.89,6070 14038.89,6190 14158.89,6310 14278.89,6430 ; 13978.89,6070 14098.89,6190 14218.89,6310 14278.89,6370 ; 14038.89,6070 14158.89,6190 14278.89,6310 ; 14098.89,6070 14218.89,6190 14278.89,6250 ; 14158.89,6070 14278.89,6190 ; 14218.89,6070 14278.89,6130
  Bottom Layer w15: 9730.09,6190 10140,6190 11079.74,6190 11939.51,6190 12589.34,6190 13159.2,6190 14278.89,6190 ; 9730.09,6310 10140,6310 11079.74,6310 11939.51,6310 12589.34,6310 13159.2,6310 14278.89,6310 ; 9730.09,6430 10140,6430 11079.74,6430 11939.51,6430 12589.34,6430 13159.2,6430 14278.89,6430 ; 9730.09,6550 10140,6550 11079.74,6550 11939.51,6550 12589.34,6550 13159.2,6550 14278.89,6550 ; 9730.09,6670 10140,6670 11079.74,6670 11939.51,6670 12589.34,6670 13159.2,6670 14278.89,6670 ; 9730.09,6790 10140,6790 11079.74,6790 11939.51,6790 12589.34,6790 13159.2,6790 14278.89,6790 ; 9730.09,6910 10140,6910 11079.74,6910 11939.51,6910 12589.34,6910 13159.2,6910 14278.89,6910 ; 9730.09,7030 10140,7030 11079.74,7030 11939.51,7030 12589.34,7030 13159.2,7030 14278.89,7030 ; 9730.09,7150 10140,7150 11079.74,7150 11939.51,7150 12589.34,7150 13159.2,7150 14278.89,7150 ; 9730.09,7270 10140,7270 11079.74,7270 11939.51,7270 12589.34,7270 13159.2,7270 14278.89,7270 ; 9730.09,7390 14278.89,7390 ; 10140,7510 10140,6070 ; 11079.74,7510 11079.74,6070 ; 11939.51,7510 11939.51,6070 ; 12589.34,7510 12589.34,6070 ; 13159.2,7510 13159.2,6070 ; 10140,6070 9730.09,6070 9730.09,7510 14278.89,7510 14278.89,6070 13159.2,6070 ; 10140,6070 11079.74,6070 ; 11079.74,6070 11939.51,6070 ; 11939.51,6070 12589.34,6070 ; 12589.34,6070 13159.2,6070

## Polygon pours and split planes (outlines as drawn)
VIN on Signal Layer 1 "Signal Layer 1-No Net" (solid, remove dead copper, pour order 14): 261,1785 262,1786 1326,1786 1326,1554 1325.07,1554.93 1325.07,1409.93 1327,1408 1318,1399 1113,1399 1113,1260 1112,1261 995,1261 968,1261 967,1262 967,1547 716,1547 713,1550 715,1548 715,1437 266,1437 260,1437 260,1443 261,1444 10.39,1437 10.39,1610 10.39,1785
GND on Signal Layer 1 "Signal Layer 1-No Net 3" (solid, remove dead copper, pour order 24): 0,2920 2010,2920 2010,0 0,0 0,2920
VIN on Top Layer "Top Layer-No Net" (solid, remove dead copper, pour order 15): 983.91,1045.45 1127.91,1045.45 1128.91,1046.45 1128.91,1183.45 1333.91,1183.45 1338.22,1187.76 1341.91,1191.45 1341.91,1569.45 1075.87,1569.45 1070.91,1564.49 1055.95,1439.45 1066.13,1357.81 1054.27,1319.45 988.9,1319.45 980.91,1311.46 982.91,1309.46 982.91,1046.45
12VOUT on Top Layer "Top Layer-No Net 1" (solid, remove dead copper, pour order 20): 1095,2895.83 1515.86,2895.83 1869.35,2895.83 1869.35,2542.35 1869.35,2115.86 1515.86,2115.86 1515,2115 1510,2120 615,2120 843.78,2120 843.78,2254 843.78,2372 842.58,2372.04 842.55,2379.78 843.78,2379.83 843.71,2376.06 847.7,2375.92 843.78,2315 829.38,2306.46 843.78,2254 843.78,2379.83 1095,2379.83 1095,2895
GND on Top Layer "Signal Layer 1-No Net 2" (solid, remove dead copper, pour order 23): 0,2920 2010,2920 2010,0 0,0 0,2910
NetC7_1 on Top Layer "Top Layer-No Net 3" (solid, remove dead copper, pour order 16): 25.26,2105.58 25.68,2106 25.26,2496.54 597.54,2496.54 838,2496.54 838,2104.97 1312.28,2106 1312.28,1788.72 1313,1788 1309.54,1784.54 1309.54,1552.11 1216.17,1552.11 1122.8,1552.11 1122.8,1603.78 1081.03,1603.78 1063.43,1603.52 1021.22,1599.88 1022,1598 1021,1597 1037.5,1597 1037.5,1512.5 1037.5,1421.5 1022,1421.5 726.5,1421.5 424,1421.5 424,1597 424,1687 425,1688 419,1682 193,1682 193,1955 195,1957 191.8,1960.2 25.26,1960.2 25.26,2104.8
VIN on Top Layer "Top Layer-No Net 4" (solid, remove dead copper, pour order 19): 25.26,1950 182.8,1950 182.8,1673.2 184,1672 184.2,1671.8 413.8,1671.8 413.8,1419.2 421,1412 403.3,1429.7 25.26,1429.7 25.26,1946.95
NetQ2_1 on Top Layer "Top Layer-No Net 2" (solid, remove dead copper, pour order 21): 439,1424.11 987,1424.11 987,1379.11 984,1376.11 982.78,1374.88 982.78,1331.4 939.29,1331.4 895.81,1331.4 895.81,1153.91 895,1153.11 893.39,1151.49 744.69,1151.49 744.69,1173.05 746,1174.37 741.26,1179.11 628,1179.11 628,1017.11 626,1015.11 437,1015.11 437,1422.11
12VOUT on Bottom Layer "Bottom Layer-No Net 2" (solid, remove dead copper, pour order 22): 1095,2895 1096,2894 1857,2894 1857,2131 1841,2147 553,2147 553,2364 569,2380 569.17,2379.83 1095,2379.83 1095,2895
VIN on Bottom Layer "Bottom Layer-No Net" (solid, remove dead copper, pour order 18): 990.91,1559.45 990.91,1044.45 1130.91,1044.45 1130.91,1184.45 1379.77,1184.45 1379.77,1555.59 1375.91,1559.45 990.91,1559.45
GND on Bottom Layer "Bottom Layer-No Net 1" (solid, remove dead copper, pour order 25): 0,2920 2005,2920 2005,5 2010,0 5,0 5,2910 0,2915
VIN on Bottom Layer "Bottom Layer-No Net 3" (solid, remove dead copper, pour order 17): 6,1994 10.39,1989.61 10.39,1415 953,1415 955,1417 969.01,1402.99 969.01,1222.32 1422.82,1222.32 1648.08,1222.32 1647.97,1376.25 1648.08,1793 227,1793 227,1996 1.77,1996 0,1994.23
GND on Signal Layer 2 "Signal Layer 2-No Net" (solid, remove dead copper, pour order 26): 0,2920 2010,2920 2010,0 0,0 0,2920

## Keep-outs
Keep-Out Layer:
  lines w10: -5,0 ccw(c0,0) 0,-5 ; -5,0 ccw(c0,0) 0,-5 ; -5,0 -5,3000 ; -5,3000 cw(c0,3000) 0,3005 ; -5,3000 cw(c0,3000) 0,3005 ; 0,-5 2000,-5 ; 0,3005 2000,3005 ; 2000,-5 ccw(c2000,0) 2005,0 ; 2000,-5 ccw(c2000,0) 2005,0 ; 2000,3005 cw(c2000,3000) 2005,3000 ; 2000,3005 cw(c2000,3000) 2005,3000 ; 2005,0 2005,3000
  text ".Layer_Name" at 577,-858.49 h60

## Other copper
Top Layer:
  text ".Layer_Name" at 577,-858.49 h60
Bottom Layer:
  text "Layer" at 9790.09,7420 h60
  text "Name" at 10200,7420 h60
  text "Material" at 11139.74,7420 h60
  text "Thickness" at 11999.51,7420 h60
  text "Constant" at 12649.34,7420 h60
  text "Board Layer Stack" at 13219.2,7420 h60
  text "1" at 9790.09,7300 h60
  text "Top Overlay" at 10200,7300 h60
  text "2" at 9790.09,7180 h60
  text "Top Solder" at 10200,7180 h60
  text "Solder Resist" at 11139.74,7180 h60
  text "0.40mil" at 11999.51,7180 h60
  text "3.5" at 12649.34,7180 h60
  text "3" at 9790.09,7060 h60
  text "Top Layer" at 10200,7060 h60
  text "Copper" at 11139.74,7060 h60
  text "2.80mil" at 11999.51,7060 h60
  text "4" at 9790.09,6940 h60
  text "Dielectric1" at 10200,6940 h60
  text "FR-4" at 11139.74,6940 h60
  text "59.20mil" at 11999.51,6940 h60
  text "4.8" at 12649.34,6940 h60
  text "5" at 9790.09,6820 h60
  text "Signal Layer 1" at 10200,6820 h60
  text "Copper" at 11139.74,6820 h60
  text "2.80mil" at 11999.51,6820 h60
  text "6" at 9790.09,6700 h60
  text "Dielectric 3" at 10200,6700 h60
  text "5.00mil" at 11999.51,6700 h60
  text "4.2" at 12649.34,6700 h60
  text "7" at 9790.09,6580 h60
  text "Signal Layer 2" at 10200,6580 h60
  text "Copper" at 11139.74,6580 h60
  text "2.80mil" at 11999.51,6580 h60
  text "8" at 9790.09,6460 h60
  text "Dielectric 2" at 10200,6460 h60
  text "10.00mil" at 11999.51,6460 h60
  text "4.2" at 12649.34,6460 h60
  text "9" at 9790.09,6340 h60
  text "Bottom Layer" at 10200,6340 h60
  text "Copper" at 11139.74,6340 h60
  text "2.80mil" at 11999.51,6340 h60
  text "10" at 9790.09,6220 h60
  text "Bottom Solder" at 10200,6220 h60
  text "Solder Resist" at 11139.74,6220 h60
  text "0.40mil" at 11999.51,6220 h60
  text "3.5" at 12649.34,6220 h60
  text "11" at 9790.09,6100 h60
  text "Bottom Overlay" at 10200,6100 h60
  text ".Layer_Name" at 577,-858.49 h60

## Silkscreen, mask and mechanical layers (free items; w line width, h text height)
Top Overlay:
  lines w10: 526.04,2319.99 546,2380 ; 526.96,869.99 547,810 ; 536,2379.99 556,2380.01 ; 537,809.99 557,810.01 ; 546.32,1870.92 546,2380 ; 546.68,1319.08 547,810 ; 566.04,2320.01 546,2380 ; 566.96,870.01 547,810 ; 611,610 611,630 ; 671,600 611,620 ; 671,640 611,620 ; 970.06,620 611,620 ; 1351.94,620 1711,620 ; 1651,600 1711,620 ; 1651,640 1711,620 ; 1711,610 1711,630 ; 609.6,807.51 1709.6,807.51 1709.6,2377.51 609.6,2377.51 609.6,807.51
  text "1570 (mil)" at 510.34,1860.89 h60 r270.04
  text "1100mil" at 980.06,584.01 h60
  text ".PRJ_Number" at 94,68 h60
  text ".PCB_Rev" at 642,68 h60
  text "©" at 710,60 h105
  text ".CopyrightYear" at 850,60 h60
  text "-" at 590,59 h60
  text ".Layer_Name" at 577,-858.49 h60
Bottom Overlay:
  text "MADE IN U.S." at 731,64 h60
  text ".Layer_Name" at 577,-858.49 h60
Top Paste:
  text ".Layer_Name" at 577,-858.49 h60
Bottom Paste:
  text ".Layer_Name" at 577,-858.49 h60
Top Solder:
  text ".Layer_Name" at 577,-858.49 h60
  text ".Layer_Name" at 577,-858.49 h60
Bottom Solder:
  text ".Layer_Name" at 577,-858.49 h60
Drill Guide:
  text ".Layer_Name" at 577,-858.49 h60
M1 Board Outline:
  the board outline again, w10
  text ".Layer_Name" at 577,-858.49 h60
M2 Board Dimensions:
  rectangle: 125,-400 500,-275
  rectangle: 0,-275 125,-150
  lines w7: 0,-275 1000,-275 ; 125,-400 125,-150 ; 250,-400 250,-150 ; 500,-400 500,-150 ; 750,-400 750,-150 ; 0,-400 0,-150 1000,-150 1000,-400 0,-400
  text ".Layer_Name" at 577,-858.49 h60
M3 3D STEP Top:
  text ".Layer_Name" at 577,-858.49 h60
M4 3D STEP Bottom:
  text ".Layer_Name" at 577,-858.49 h60
M5 Assembly Top:
  lines w10: -292,-930.17 6308,-930.17 ; -292,-726.83 6310,-726.83 ; -292,-523.5 -292,-1133.5 3713,-1133.5 6310,-1133.5 6310,-523.5 -291.5,-523.5 -291.5,-1133.5 1284,-1133.5 ; 2173,-1133.5 2173,-523.5 ; 3440,-726.83 3440,-523.5 ; 4280,-726.83 4280,-523.5 ; 4902,-1140 4902,-937.17
  text "COMPONENTS MARKED 'DNP' SHOULD NOT BE POPULATED." at 1153.5,-318.5 h60
  text "ASSEMBLY VARIANT:" at 1153,-434 h60
  text ".VariantName" at 2189,-434 h60
  text "PCB VIEWED FROM TOP SIDE" at -228.5,-655.67 h60
  text "BOARD #:" at 2248,-655.67 h60
  text ".PRJ_Number" at 2793.5,-655.67 h60
  text "REV:" at 3638,-655.67 h60
  text ".PCB_Rev" at 3929.5,-655.67 h60
  text "SVN REV:" at 4476,-655.67 h60
  text ".VersionControl_RevNumber" at 4982,-655.67 h60
  text "PLOT NAME =" at -228.5,-1064.34 h60
  text ".plot_File_Name" at 577,-1064.34 h60
  text "GENERATED    :" at 2250,-1064.34 h60
  text ".Print_Date" at 3119.5,-1064.34 h60
  text ".Print_Time" at 3848.5,-1064.34 h60
  text "TEXAS INSTRUMENTS" at 5113,-1064.34 h60
M6 Assembly Bottom:
  lines w10: -292.5,-727.33 6309.5,-727.33 ; -290.5,-930.67 6309.5,-930.67 ; 1115.5,-1140.5 1115.5,-937.67 ; 1737.5,-727.33 1737.5,-524 ; 2577.5,-727.33 2577.5,-524 ; 3844.5,-1134 3844.5,-524 ; 4733.5,-1134 6309,-1134 6309,-524 -292.5,-524 -292.5,-1134 2304.5,-1134 6309.5,-1134 6309.5,-524
  text "COMPONENTS MARKED 'DNP' SHOULD NOT BE POPULATED." at 6102,-318 h60
  text ".VariantName" at 5058,-434 h60
  text "ASSEMBLY VARIANT:" at 6097,-434 h60
  text ".VersionControl_RevNumber" at 1035.5,-656.17 h60
  text "SVN REV:" at 1541.5,-656.17 h60
  text ".PCB_Rev" at 2088,-656.17 h60
  text "REV:" at 2379.5,-656.17 h60
  text ".PRJ_Number" at 3224,-656.17 h60
  text "BOARD #:" at 3769.5,-656.17 h60
  text "PCB VIEWED FROM BOTTOM SIDE" at 6246,-656.17 h60
  text "TEXAS INSTRUMENTS" at 904.5,-1064.84 h60
  text ".Print_Time" at 2169,-1064.84 h60
  text ".Print_Date" at 2898,-1064.84 h60
  text "GENERATED    :" at 3767.5,-1064.84 h60
  text ".plot_File_Name" at 5440.5,-1064.84 h60
  text "PLOT NAME =" at 6246,-1064.84 h60
M9 Title Sheet:
  drawing of 57 lines, arcs and shapes, not listed
  text "1" at 739.84,8036.5 h70
  text "2" at 3235.5,8036.5 h70
  text "3" at 5724.84,8036.5 h70
  text "4" at 8231.51,8036.5 h70
  text "5" at 10730.5,8036.5 h70
  text "6" at 13235.5,8036.5 h70
  text "A" at -416.5,6893.5 h70
  text "A" at 14383.5,6893.5 h70
  text "B" at -416.5,4513.5 h70
  text "B" at 14383.5,4513.5 h70
  text "C" at -416.5,2138.5 h70
  text "C" at 14383.5,2138.5 h70
  text "PROJECT TITLE:" at 11343.5,277.5 h45
  text ".PRJ_Title" at 11393.5,144.17 h70
  text "DESIGNED FOR:" at 11343.5,-23.5 h45
  text ".PRJ_Customer" at 11393.5,-163.5 h70
  text "D" at -416.5,-231.5 h70
  text "D" at 14383.5,-231.5 h70
  text "FILE NAME:" at 11343.5,-323.5 h45
  text ".PCB_File_Name_No_Path" at 11393.5,-443.5 h70
  text "Texas Instruments (TI) and/or its licensors do not warrant the accuracy or completeness of this specification" at 6374,-605.34 h45
  text "ENGINEER:" at 11343.5,-613.5 h45
  text "LAYOUT BY:" at 12848.5,-613.5 h45
  text "or any information contained therein. TI and/or its licensors do not warrant that this design will meet" at 6329.01,-718 h45
  text ".PRJ_Engineer" at 11393.5,-768.49 h70
  text ".PCB_Layout" at 12899,-768.49 h70
  text "the specifications, will be suitable for your application or fit for any particular purpose, or will operate in" at 6329.01,-830.67 h45
  text ".Layer_Name" at 577,-858.49 h60
  text "ALTIUM DESIGNER VERSION:" at 12848.5,-923.5 h45
  text "an implementation. TI and/or its licensors do not warrant that the design is production worthy. You should" at 6329.01,-943.33 h45
  text "completely validate and test your design implementation to confirm the system functionality for your application." at 6374,-1056 h45
  text ".print_Scale" at 11393.5,-1056.83 h70
  text ".Application_BuildNumber" at 12899,-1056.83 h70
  text "1" at 739.84,-1263.5 h70
  text "2" at 3235.5,-1263.5 h70
  text "3" at 5724.84,-1263.5 h70
  text "4" at 8231.51,-1263.5 h70
  text "5" at 10730.5,-1263.5 h70
  text "6" at 13235.5,-1263.5 h70
M10 Fab Notes:
  drawing of 185 lines, arcs and shapes, not listed
  text "DESIGN INFORMATION" at 12381.02,5910 h60
  text "MIN. TRACK WIDTH:" at 11736.46,5730 h60
  text "8" at 12832.7,5730 h60
  text "MIL" at 12987.46,5730 h60
  text "MIN. CLEARANCE:" at 11736.46,5598 h60
  text "0.2" at 12772.7,5598 h60
  text "mm" at 12987.46,5598 h60
  text "MIN. VIA PAD SIZE:" at 11736.46,5466 h60
  text "24" at 12802.71,5466 h60
  text "MIL" at 12987.46,5466 h60
  text "0.05mm (2MIL)" at 12431.46,5324.29 h60
  text "MINIMUM ANNULAR RING" at 11407.23,5320 h60
  text "EXTERNAL" at 13139.46,5320 h60
  text "PER" at 11607.23,5202 h60
  text "IPC-D-275 CLASS 2 LEVEL C" at 11827.23,5202 h60
  text "MIL, HOLES" at 13315.46,5089.71 h60
  text "+/-" at 12923,5089 h60
  text "+/-" at 13777,5089 h60
  text "REGISTRATION TOLERANCES:" at 11407.23,5084 h60
  text "METAL" at 12607,5084 h60
  text "5" at 13183.2,5084 h60
  text "3" at 14016.2,5084 h60
  text "MIL" at 14132.46,5084 h60
  text "MATERIAL:" at 11332.46,4874.54 h60
  text "FR-4 High Tg" at 12318.9,4734.21 h60
  text "FR-408" at 11753.46,4725.64 h60
  text "X" at 12165.46,4725.64 h60
  text "OTHER" at 13241.46,4725.64 h60
  text "62 MIL (1.6mm) +/-10%" at 12073.56,4562.92 h60
  text "THICKNESS:" at 11407.23,4558.64 h60
  text "X" at 11945.4,4558.64 h60
  text "OTHER" at 13358.46,4558.64 h60
  text "TOLERANCE:" at 11407.23,4400.64 h60
  text "X" at 12246.53,4400.64 h60
  text "ANSI IPC-6012 TYPE 3 CLASS 2" at 12433.48,4400.64 h60
  text "OTHER +/-" at 12433.46,4244.64 h60
  text "BOW & TWIST:" at 11407.23,4087.64 h60
  text "X" at 12246.53,4087.64 h60
  text "ANSI IPC-6012 TYPE 3 CLASS 2" at 12433.48,4087.64 h60
  text "OTHER +/-" at 12433.46,3929.13 h60
  text "DRILLING:" at 11332.46,3790.64 h60
  text "REFERENCE:" at 11407.23,3673.64 h60
  text "X" at 12055.46,3673.64 h60
  text "AS SHOWN" at 12242.46,3673.64 h60
  text "X" at 12956.46,3673.64 h60
  text "NC_DRILL FILES" at 13093.46,3673.64 h60
  text "PTH MIN COPPER THICKNESS:" at 11407.23,3515.64 h60
  text "X" at 12757.46,3515.64 h60
  text "1MIL" at 12894.46,3515.64 h60
  text "OTHER" at 13391.46,3515.64 h60
  text "BOARD FINISH:" at 11332.46,3356.64 h60
  text "SILKSCREEN:" at 11487.68,3238.64 h60
  text "X" at 12436.46,3238.64 h60
  text "TOP" at 12562.46,3238.64 h60
  text "X" at 12946.46,3238.64 h60
  text "BOTTOM" at 13073.46,3238.64 h60
  text "SILKSCREEN COLOR:" at 11487.68,3071.64 h60
  text "X" at 12435.42,3071.64 h60
  text "WHITE" at 12562.46,3071.64 h60
  text "OTHER" at 13073.46,3071.64 h60
  text "SOLDER RESIST COLOR:" at 11487.68,2901.64 h60
  text "X" at 12055.42,2742.44 h60
  text "GREEN" at 12182.46,2742.44 h60
  text "BLUE" at 12773.46,2742.44 h60
  text "OTHER" at 13311.46,2742.44 h60
  text "IMMERSION GOLD (ENIG)" at 12393.46,2553.92 h60
  text "ENEPIG" at 13731,2550.64 h60
  text "SURFACE FINISH:" at 11332.46,2549.64 h60
  text "X" at 12206.51,2549.64 h60
  text "IMM. TIN/SILVER OR EQUIV" at 11662,2392.64 h60
  text "OTHER" at 13093.46,2392.64 h60
  text "ARRAY/PANEL:" at 11332.46,2213.64 h60
  text "CUT AND TRIM PER MECH LAYER 1" at 12393.46,2209.35 h60
  text "N.C. ROUTE" at 12393.46,2057.64 h60
  text "X" at 13072.46,2057.64 h60
  text "V. SCORE" at 13259.46,2057.64 h60
  text "CERTIFICATION:" at 11332.46,1920.64 h60
  text "MATERIALS AND WORKMANSHIP FOR ALL PCBS" at 12057.46,1920.64 h60
  text "TO MEET OR EXCEED THE REQUIREMENTS OF:" at 12057.46,1822.64 h60
  text "X" at 11683.96,1686.13 h60
  text "ANSI IPC-A-600F CLASS ->" at 11822.96,1686.13 h60
  text "X" at 13462.02,1686.13 h60
  text "2" at 13580.96,1686.14 h60
  text "1" at 13265.96,1684.64 h60
  text "3" at 13934.96,1684.64 h60
  text "X" at 11686.02,1526.64 h60
  text "UL 94V-0" at 11822.96,1526.64 h60
  text "X" at 12498.02,1526.64 h60
  text "RoHS" at 12634.96,1526.64 h60
  text "OTHER" at 13279.36,1526.64 h60
  text "PER ORDER" at 13676.42,1526.64 h60
  text "ADDITIONAL REQUIREMENTS:" at 11332.46,1385.64 h60
  text "MICROSECTION:" at 11407.23,1270.64 h60
  text "YES" at 12312.96,1270.64 h60
  text "REQUIRED" at 13174.46,1114.49 h60
  text "BARE BOARD ELEC. TEST:" at 11407.23,1111.64 h60
  text "NONE" at 12712.96,1111.64 h60
  text "X" at 13047.46,1111.64 h60
  text "PER ORDER" at 13766.46,1111.64 h60
  text "MANUFACTURER'S UL:" at 11407.23,954.64 h60
  text "RAIL" at 12572.96,950.35 h60
  text "METAL" at 13064.77,950.35 h60
  text "X" at 13440,950 h60
  text "SILK" at 13576.46,950.35 h60
  text ".Layer_Name" at 577,-858.49 h60
M11 Gerber Information:
  lines w10: -292,-930.17 6308,-930.17 ; -292,-726.83 6310,-726.83 ; -292,-523.5 -292,-1133.5 3713,-1133.5 6310,-1133.5 6310,-523.5 -291.5,-523.5 -291.5,-1133.5 1284,-1133.5 ; 2173,-1133.5 2173,-523.5 ; 3440,-726.83 3440,-523.5 ; 4280,-726.83 4280,-523.5 ; 4902,-1140 4902,-937.17
  text "ALL ARTWORK VIEWED FROM TOP SIDE" at -228.5,-655.67 h60
  text "BOARD #:" at 2248,-655.67 h60
  text ".PRJ_Number" at 2793.5,-655.67 h60
  text "REV:" at 3638,-655.67 h60
  text ".PCB_Rev" at 3929.5,-655.67 h60
  text "SVN REV:" at 4476,-655.67 h60
  text ".VersionControl_RevNumber" at 4982,-655.67 h60
  text "LAYER NAME =" at -228.5,-858.49 h60
  text "PLOT NAME =" at -228.5,-1064.34 h60
  text ".plot_File_Name" at 577,-1064.34 h60
  text "GENERATED    :" at 2250,-1064.34 h60
  text ".Print_Date" at 3119.5,-1064.34 h60
  text ".Print_Time" at 3848.5,-1064.34 h60
  text "TEXAS INSTRUMENTS" at 5113,-1064.34 h60
M12 Stackup:
  text ".Layer_Name" at 577,-858.49 h60
M13 Component Bodies Top:
  text ".Layer_Name" at 577,-858.49 h60
M14 Component Bodies Bottom:
  text ".Layer_Name" at 577,-858.49 h60
M15 Courtyards Top:
  text ".Layer_Name" at 577,-858.49 h60
M16 Courtyards Bottom:
  text ".Layer_Name" at 577,-858.49 h60
Drill Drawing:
  circle w1: c2292.72,1291.04 r24.89
  lines w1: 2267.83,233.36 2280.27,233.36 2280.27,220.92 2305.16,220.92 2305.16,233.36 2317.6,233.36 2317.6,258.25 2305.16,258.25 2305.16,270.69 2280.27,270.69 2280.27,258.25 2267.83,258.25 2267.83,233.36 ; 2267.83,370.24 2292.72,382.68 2317.6,370.24 2305.16,395.12 2317.6,420.01 2292.72,407.57 2267.83,420.01 2280.27,395.12 2267.83,370.24 ; 2267.83,532 2280.27,532 2292.72,519.56 2305.16,532 2317.6,532 2305.16,544.44 2317.6,556.89 2305.16,556.89 2292.72,569.33 2280.27,556.89 2267.83,556.89 2280.27,544.44 2267.83,532 ; 2267.83,718.65 2317.6,718.65 2292.72,668.88 2267.83,718.65 ; 2267.83,843.08 2292.72,818.2 2317.6,843.08 2292.72,867.97 2267.83,843.08 ; 2267.83,967.52 2317.6,967.52 2317.6,1017.29 2267.83,1017.29 2267.83,967.52 ; 2267.83,1116.84 2267.83,1129.28 2280.27,1141.72 2267.83,1154.17 2267.83,1166.61 2280.27,1166.61 2292.72,1154.17 2305.16,1166.61 2317.6,1166.61 2317.6,1154.17 2305.16,1141.72 2317.6,1129.28 2317.6,1116.84 2305.16,1116.84 2292.72,1129.28 2280.27,1116.84 2267.83,1116.84
  lines w12: 2200,176.12 4318.02,176.12 ; 2200,1370.68 4318.02,1370.68 ; 2570.36,26.8 2570.36,1520 ; 2927.36,26.8 2927.36,1520 ; 3588.93,26.8 3588.93,1520 ; 3873.07,26.8 3873.07,1520 ; 2200,26.8 4318.02,26.8 4318.02,1520 2200,1520 2200,26.8
  text "Symbol" at 2289.59,1415.48 h72
  text "Quantity" at 2615.16,1415.48 h72
  text "Finished Hole Size" at 2972.16,1415.48 h72
  text "Plated" at 3633.72,1415.48 h72
  text "Hole Type" at 3917.86,1415.48 h72
  text "12" at 2615.16,1266.16 h60
  text "7.87mil (0.200mm)" at 2972.16,1266.16 h60
  text "PTH" at 3633.72,1266.16 h60
  text "Round" at 3917.86,1266.16 h60
  text "48" at 2615.16,1116.84 h60
  text "12.00mil (0.305mm)" at 2972.16,1116.84 h60
  text "PTH" at 3633.72,1116.84 h60
  text "Round" at 3917.86,1116.84 h60
  text "1" at 2615.16,967.52 h60
  text "16.00mil (0.406mm)" at 2972.16,967.52 h60
  text "PTH" at 3633.72,967.52 h60
  text "Round" at 3917.86,967.52 h60
  text "28" at 2615.16,818.2 h60
  text "28.00mil (0.711mm)" at 2972.16,818.2 h60
  text "PTH" at 3633.72,818.2 h60
  text "Round" at 3917.86,818.2 h60
  text "6" at 2615.16,668.88 h60
  text "40.00mil (1.016mm)" at 2972.16,668.88 h60
  text "PTH" at 3633.72,668.88 h60
  text "Round" at 3917.86,668.88 h60
  text "2" at 2615.16,519.56 h60
  text "51.18mil (1.300mm)" at 2972.16,519.56 h60
  text "PTH" at 3633.72,519.56 h60
  text "Round" at 3917.86,519.56 h60
  text "2" at 2615.16,370.24 h60
  text "62.99mil (1.600mm)" at 2972.16,370.24 h60
  text "PTH" at 3633.72,370.24 h60
  text "Round" at 3917.86,370.24 h60
  text "4" at 2615.16,220.92 h60
  text "63.00mil (1.600mm)" at 2972.16,220.92 h60
  text "PTH" at 3633.72,220.92 h60
  text "Round" at 3917.86,220.92 h60
  text "103 Total" at 2615.16,71.6 h60
  text ".Layer_Name" at 577,-858.49 h60

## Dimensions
0,0 to 2000,0 on M2 Board Dimensions
0,-400 to 1000,-400 on M2 Board Dimensions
